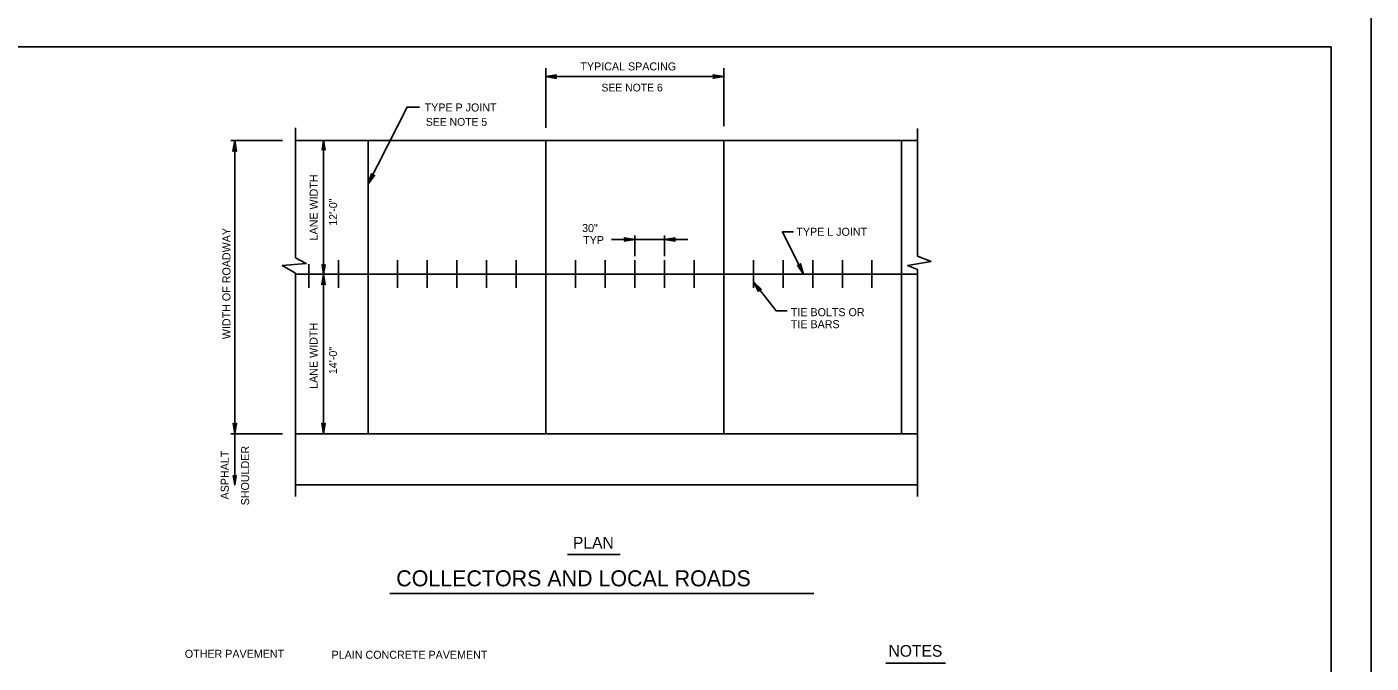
# Model space of a CAD drawing. Extents: x 637877 to 639321, y 297902 to 299090.
# Drawn here: x 638753 to 639257, y 298250 to 298488 of the extents above; entities that cross this region are included whole.
import ezdxf

# ---------------------------------------------------------------- set-up
doc = ezdxf.new("R2010")
doc.units = 0
for name, color, linetype in [('1', 7, 'Continuous'), ('2', 7, 'Continuous'), ('3', 7, 'Continuous'), ('PLT-BNDY', 7, 'Continuous')]:
    doc.layers.add(name, color=color, linetype=linetype)

msp = doc.modelspace()

# ---------------------------------------------------------------- linework, layer by layer
at = {"layer": '1'}
for points in [[(639241.51, 297916.57), (639241.51, 298480.57), (638455.51, 298480.57), (638455.51, 297916.57), (639241.51, 297916.57), (639241.51, 297942.93), (639041.51, 297942.93), (639041.51, 298007.61), (639241.51, 298007.61), (639241.51, 298036.57), (639041.51, 298036.57), (639041.51, 297916.57), (639120.32, 297916.57), (639120.32, 297942.93), (639120.32, 297916.57), (639197.32, 297916.57), (639197.32, 297942.93), (639197.32, 297930.61), (639241.51, 297930.61)], [(638863.5, 298442.12), (638863.74, 298442.25), (638863.91, 298445.43), (638863.5, 298442.12), (638863.35, 298441.95), (638863.91, 298445.43), (638864.07, 298442.25), (638864.31, 298442.13), (638863.91, 298445.43), (638864.47, 298441.95), (638864.31, 298442.13)], [(638864.33, 298398.75), (638864.09, 298398.62), (638863.91, 298395.43), (638864.33, 298398.75), (638864.47, 298398.92), (638863.91, 298395.43), (638863.75, 298398.62), (638863.52, 298398.74), (638863.91, 298395.43), (638863.36, 298398.92), (638863.52, 298398.74)], [(638831.04, 298319.71), (638830.8, 298319.59), (638830.62, 298316.4), (638831.04, 298319.71), (638831.18, 298319.88), (638830.62, 298316.4), (638830.46, 298319.58), (638830.23, 298319.7), (638830.62, 298316.4), (638830.07, 298319.88), (638830.23, 298319.7)]]:
    msp.add_lwpolyline(points, dxfattribs=at)
at = {"layer": '2'}
for p, q in [((638947.24, 298450.25), (638947.24, 298472.6)), ((639013.91, 298450.83), (639013.91, 298472.6)), ((638947.24, 298469.42), (639013.91, 298469.42)), ((638853.41, 298450.27), (638853.41, 298401.52)), ((639086.51, 298450.04), (639086.51, 298402.13)), ((638848.55, 298445.43), (638829.16, 298445.43)), ((638830.62, 298445.43), (638830.62, 298318.62)), ((638853.41, 298445.43), (639086.51, 298445.43)), ((638863.91, 298445.43), (638863.91, 298395.43)), ((638880.58, 298445.43), (638880.58, 298335.51)), ((638947.24, 298445.43), (638947.24, 298335.51)), ((639013.91, 298445.43), (639013.91, 298335.51)), ((639080.57, 298445.43), (639080.57, 298335.51)), ((638991.69, 298408.42), (638971.82, 298408.42)), ((638980.57, 298402.1), (638980.57, 298409.87)), ((638991.69, 298402.1), (638991.69, 298409.87)), ((639000.43, 298408.42), (638991.69, 298408.42)), ((638853.41, 298395.71), (638853.41, 298312.1)), ((639086.51, 298397.11), (639086.51, 298312.1)), ((638853.41, 298395.43), (639086.51, 298395.43)), ((638857.35, 298395.43), (638857.59, 298395.43)), ((638858.36, 298395.43), (638858.36, 298395.43)), ((638863.91, 298395.43), (638863.91, 298335.51)), ((638863.91, 298395.43), (638863.91, 298395.43)), ((638875.02, 298395.43), (638875.02, 298395.43)), ((638880.58, 298395.43), (638880.58, 298395.43)), ((638886.13, 298395.43), (638886.13, 298395.43)), ((638886.13, 298395.43), (638886.13, 298395.43)), ((638886.13, 298395.43), (638886.13, 298395.43)), ((638886.13, 298395.43), (638886.13, 298395.43)), ((638886.13, 298395.43), (638886.13, 298395.43)), ((638891.69, 298395.43), (638891.69, 298395.43)), ((638897.24, 298395.43), (638897.24, 298395.43)), ((638902.8, 298395.43), (638902.8, 298395.43)), ((638908.36, 298395.43), (638908.36, 298395.43)), ((638913.91, 298395.43), (638913.91, 298395.43)), ((638919.47, 298395.43), (638919.47, 298395.43)), ((638925.02, 298395.43), (638925.02, 298395.43)), ((638930.58, 298395.43), (638930.58, 298395.43)), ((638936.13, 298395.43), (638936.13, 298395.43)), ((638941.69, 298395.43), (638941.69, 298395.43)), ((638952.8, 298395.43), (638952.8, 298395.43)), ((638952.8, 298395.43), (638952.8, 298395.43)), ((638952.8, 298395.43), (638952.8, 298395.43)), ((638958.35, 298395.43), (638958.35, 298395.43)), ((638963.91, 298395.43), (638963.91, 298395.43)), ((638969.46, 298395.43), (638969.46, 298395.43)), ((638975.02, 298395.43), (638975.02, 298395.43)), ((638980.57, 298395.43), (638980.57, 298395.43)), ((638986.13, 298395.43), (638986.13, 298395.43)), ((638991.69, 298395.43), (638991.69, 298395.43)), ((638997.24, 298395.43), (638997.24, 298395.43)), ((639002.8, 298395.43), (639002.8, 298395.43)), ((639008.35, 298395.43), (639008.35, 298395.43)), ((639013.91, 298395.43), (639013.91, 298395.43)), ((639019.46, 298395.43), (639019.46, 298395.43)), ((639019.46, 298395.43), (639019.46, 298395.43)), ((639019.46, 298395.43), (639019.46, 298395.43)), ((639019.46, 298395.43), (639019.46, 298395.43)), ((639019.46, 298395.43), (639019.46, 298395.43)), ((639025.02, 298395.43), (639025.02, 298395.43)), ((639030.57, 298395.43), (639030.57, 298395.43)), ((639036.13, 298395.43), (639036.13, 298395.43)), ((639041.68, 298395.43), (639041.68, 298395.43)), ((639047.24, 298395.43), (639047.24, 298395.43)), ((639052.79, 298395.43), (639052.79, 298395.43)), ((639058.35, 298395.43), (639058.35, 298395.43)), ((639063.9, 298395.43), (639063.9, 298395.43)), ((639069.46, 298395.43), (639069.46, 298395.43)), ((639075.02, 298395.43), (639075.02, 298395.43)), ((639080.57, 298395.43), (639080.57, 298395.43)), ((638848.55, 298335.51), (638829.16, 298335.51)), ((638853.41, 298335.51), (639086.51, 298335.51)), ((638858.81, 298335.51), (638870.22, 298335.51)), ((638853.41, 298316.4), (639086.51, 298316.4))]:
    msp.add_line(p, q, dxfattribs=at)
for points in [[(638951.03, 298468.95), (638950.89, 298469.22), (638947.24, 298469.42), (638951.03, 298468.95), (638951.22, 298468.78), (638947.24, 298469.42), (638950.88, 298469.6), (638951.02, 298469.87), (638947.24, 298469.42), (638951.22, 298470.05), (638951.02, 298469.87)], [(639010.12, 298469.89), (639010.26, 298469.62), (639013.91, 298469.42), (639010.12, 298469.89), (639009.93, 298470.06), (639013.91, 298469.42), (639010.27, 298469.24), (639010.13, 298468.97), (639013.91, 298469.42), (639009.93, 298468.79), (639010.13, 298468.97)], [(638899.91, 298458.02), (638895.23, 298458.02), (638880.67, 298429.19)], [(638830.15, 298441.65), (638830.42, 298441.79), (638830.62, 298445.43), (638830.15, 298441.65), (638829.98, 298441.46), (638830.62, 298445.43), (638830.8, 298441.79), (638831.07, 298441.66), (638830.62, 298445.43), (638831.25, 298441.46), (638831.07, 298441.66)], [(638882.82, 298432.34), (638882.51, 298432.34), (638880.67, 298429.19), (638882.82, 298432.34), (638883.06, 298432.43), (638880.67, 298429.19), (638882.17, 298432.51), (638881.99, 298432.75), (638880.67, 298429.19), (638881.93, 298433.02), (638881.99, 298432.75)], [(639040.03, 298411.31), (639035.87, 298411.31), (639043.84, 298395.43)], [(638976.79, 298408.89), (638976.93, 298408.62), (638980.57, 298408.42), (638976.79, 298408.89), (638976.6, 298409.06), (638980.57, 298408.42), (638976.93, 298408.24), (638976.8, 298407.97), (638980.57, 298408.42), (638976.6, 298407.78), (638976.8, 298407.97)], [(638995.47, 298407.94), (638995.33, 298408.22), (638991.69, 298408.42), (638995.47, 298407.94), (638995.66, 298407.78), (638991.69, 298408.42), (638995.33, 298408.6), (638995.46, 298408.87), (638991.69, 298408.42), (638995.66, 298409.05), (638995.46, 298408.87)], [(638853.41, 298401.52), (638857.45, 298399.38), (638848.42, 298398.67), (638853.41, 298395.71)], [(638869.47, 298390.23), (638869.47, 298395.43), (638869.47, 298400.64)], [(638880.58, 298390.23), (638880.58, 298395.43), (638880.58, 298400.64)], [(638891.69, 298390.23), (638891.69, 298395.43), (638891.69, 298400.64)], [(638902.8, 298390.23), (638902.8, 298395.43), (638902.8, 298400.64)], [(638913.91, 298390.23), (638913.91, 298395.43), (638913.91, 298400.64)], [(638925.02, 298390.23), (638925.02, 298395.43), (638925.02, 298400.64)], [(638936.13, 298390.23), (638936.13, 298395.43), (638936.13, 298400.64)], [(638958.35, 298390.23), (638958.35, 298395.43), (638958.35, 298400.64)], [(638969.46, 298390.23), (638969.46, 298395.43), (638969.46, 298400.64)], [(638980.57, 298390.23), (638980.57, 298395.43), (638980.57, 298400.64)], [(638991.69, 298390.23), (638991.69, 298395.43), (638991.69, 298400.64)], [(639002.8, 298390.23), (639002.8, 298395.43), (639002.8, 298400.64)], [(639025.02, 298390.23), (639025.02, 298395.43), (639025.02, 298400.64)], [(639036.13, 298390.23), (639036.13, 298395.43), (639036.13, 298400.64)], [(639047.24, 298390.23), (639047.24, 298395.43), (639047.24, 298400.64)], [(639058.35, 298390.23), (639058.35, 298395.43), (639058.35, 298400.64)], [(639069.46, 298390.23), (639069.46, 298395.43), (639069.46, 298400.64)], [(639086.51, 298402.13), (639091.61, 298400.09), (639082.81, 298398.67), (639086.51, 298397.11)], [(638858.36, 298390.23), (638858.36, 298395.43), (638858.36, 298399.14)], [(639042.57, 298399.03), (639042.39, 298398.78), (639043.84, 298395.43), (639042.57, 298399.03), (639042.63, 298399.28), (639043.84, 298395.43), (639042.05, 298398.61), (639041.75, 298398.6), (639043.84, 298395.43), (639041.49, 298398.71), (639041.75, 298398.6)], [(638863.44, 298391.65), (638863.71, 298391.79), (638863.91, 298395.43), (638863.44, 298391.65), (638863.27, 298391.46), (638863.91, 298395.43), (638864.09, 298391.8), (638864.36, 298391.66), (638863.91, 298395.43), (638864.54, 298391.46), (638864.36, 298391.66)], [(639037.7, 298381.66), (639033.54, 298381.66), (639025.02, 298392.46)], [(639026.99, 298389.2), (639027.12, 298389.48), (639025.02, 298392.46), (639026.99, 298389.2), (639026.98, 298388.95), (639025.02, 298392.46), (639027.41, 298389.72), (639027.71, 298389.78), (639025.02, 298392.46), (639027.98, 298389.73), (639027.71, 298389.78)], [(638831.1, 298339.29), (638830.82, 298339.15), (638830.62, 298335.51), (638831.1, 298339.29), (638831.26, 298339.49), (638830.62, 298335.51), (638830.44, 298339.15), (638830.17, 298339.28), (638830.62, 298335.51), (638829.99, 298339.49), (638830.17, 298339.28)], [(638864.39, 298339.29), (638864.11, 298339.15), (638863.91, 298335.51), (638864.39, 298339.29), (638864.55, 298339.49), (638863.91, 298335.51), (638863.73, 298339.15), (638863.46, 298339.28), (638863.91, 298335.51), (638863.28, 298339.49), (638863.46, 298339.28)]]:
    msp.add_lwpolyline(points, dxfattribs=at)
at = {"layer": '3'}
for p, q in [((638955.4, 298290.36), (638975.12, 298290.36)), ((638888.78, 298275.73), (639047.68, 298275.73)), ((639074.62, 298249.66), (639097.06, 298249.66))]:
    msp.add_line(p, q, dxfattribs=at)
at = {"layer": 'PLT-BNDY'}
msp.add_lwpolyline([(638415.51, 298495.57), (639256.51, 298495.57), (639256.51, 297901.57), (638415.51, 297901.57)], close=True, dxfattribs=at)

# ---------------------------------------------------------------- texts
at = {"layer": '2'}
for s, height, p in [('TYPE P JOINT', 2.9997, (638901.8, 298456.37)), ('30"', 3, (638960.81, 298411.18)), ('TYP', 3, (638961.22, 298406.68))]:
    msp.add_text(s, height=height, dxfattribs=at).set_placement(p)
at = {"layer": '3'}
for s, height, p in [('TYPICAL SPACING', 2.9997, (638960.18, 298471.76)), ('SEE NOTE 6', 2.917, (638968.06, 298463.87)), ('SEE NOTE 5', 2.917, (638902.28, 298451.01)), ('TYPE L JOINT', 2.9997, (639041.11, 298409.78)), ('TIE BOLTS OR', 2.9997, (639039.05, 298379.65)), ('TIE BARS', 3, (639039.05, 298375.15)), ('PLAN', 4.375, (638957.4, 298292.56)), ('COLLECTORS AND LOCAL ROADS', 6, (638891.17, 298278.4)), ('OTHER PAVEMENT', 2.9997, (638811.93, 298251.61)), ('NOTES', 4.375, (639075.66, 298252.02)), ('PLAIN CONCRETE PAVEMENT', 2.9997, (638866.93, 298251.25))]:
    msp.add_text(s, height=height, dxfattribs=at).set_placement(p)
for s, height, p in [('LANE WIDTH', 3, (638861.73, 298408.03)), ('12\'-0"', 3, (638869.02, 298413.53)), ('WIDTH OF ROADWAY', 2.9997, (638829.02, 298371.03)), ('LANE WIDTH', 3, (638861.69, 298352.42)), ('14\'-0"', 3, (638868.97, 298357.92)), ('SHOULDER', 3, (638836.03, 298308.75)), ('ASPHALT', 3, (638828.4, 298310.96))]:
    msp.add_text(s, height=height, rotation=90, dxfattribs=at).set_placement(p)

doc.saveas('drawing.dxf')
